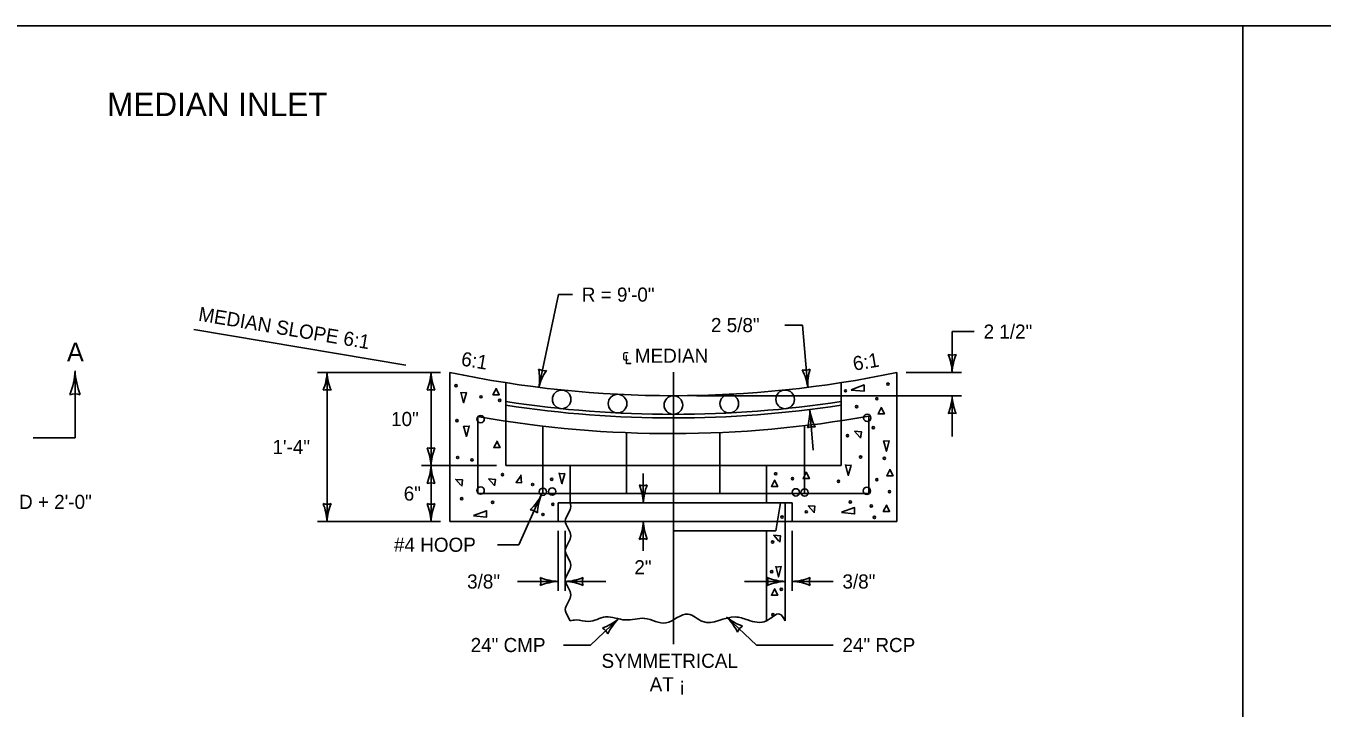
# Model space of a CAD drawing. Extents: x 49991.4 to 50021, y 49987.6 to 50011.4.
# Drawn here: x 50002.9 to 50008.4, y 49996.1 to 49999 of the extents above; entities that cross this region are included whole.
import ezdxf

# ---------------------------------------------------------------- set-up
doc = ezdxf.new("R2010")
doc.units = 0
for name, color, linetype in [('Level 1', 7, 'Continuous'), ('Level 2', 7, 'Continuous'), ('Level 3', 7, 'Continuous'), ('Level 4', 7, 'Continuous'), ('Level 5', 7, 'Continuous'), ('Level 6', 7, 'Continuous')]:
    doc.layers.add(name, color=color, linetype=linetype)

msp = doc.modelspace()

# ---------------------------------------------------------------- linework, layer by layer
at = {"layer": 'Level 1'}
for p, q in [((50008.0668, 49998.9992), (50008.0668, 49987.7988)), ((50004.6973, 49996.894), (50004.6973, 49997.5274)), ((50006.5972, 49996.894), (50006.5972, 49997.5274)), ((50004.9348, 49997.1316), (50004.9348, 49997.4839)), ((50006.3597, 49997.1316), (50006.3597, 49997.4839)), ((50004.816, 49997.0127), (50004.816, 49997.3383)), ((50005.9886, 49997.3617), (50005.9886, 49997.3617)), ((50006.4785, 49997.0127), (50006.4785, 49997.3419)), ((50005.0926, 49997.0127), (50005.0926, 49997.299)), ((50006.2049, 49997.0127), (50006.2049, 49997.3012)), ((50005.4475, 49997.0126), (50005.4475, 49997.271)), ((50005.8451, 49997.0127), (50005.8451, 49997.272)), ((50004.9348, 49997.1316), (50006.3597, 49997.1316)), ((50005.2078, 49996.9732), (50005.2078, 49997.1316)), ((50006.0431, 49996.9732), (50006.0431, 49997.1316)), ((50004.816, 49997.0127), (50006.4785, 49997.0127)), ((50005.1573, 49996.9732), (50005.1573, 49996.894)), ((50005.1573, 49996.9732), (50005.2079, 49996.9732)), ((50005.2079, 49996.9732), (50006.1222, 49996.9732)), ((50006.0826, 49996.8544), (50006.1025, 49996.9732)), ((50006.1222, 49996.9732), (50006.1222, 49996.4721)), ((50006.1222, 49996.9732), (50006.1523, 49996.9732)), ((50006.1523, 49996.9732), (50006.1523, 49996.894)), ((50005.1912, 49996.9107), (50005.2078, 49996.9441)), ((50004.6973, 49996.894), (50005.1573, 49996.894)), ((50005.2078, 49996.848), (50005.1912, 49996.8813)), ((50006.0431, 49996.8544), (50005.6472, 49996.8544)), ((50006.0431, 49996.8544), (50006.0431, 49996.4721)), ((50006.0431, 49996.8544), (50006.0826, 49996.8544)), ((50006.1523, 49996.894), (50006.5972, 49996.894)), ((50005.1912, 49996.7853), (50005.2078, 49996.8187)), ((50005.2078, 49996.7227), (50005.1912, 49996.756)), ((50005.1912, 49996.66), (50005.2078, 49996.6934)), ((50005.2078, 49996.5974), (50005.1912, 49996.6307)), ((50005.1912, 49996.5347), (50005.2078, 49996.5681)), ((50005.2078, 49996.4721), (50005.1912, 49996.5054))]:
    msp.add_line(p, q, dxfattribs=at)
msp.add_lwpolyline([(49999.3835, 49998.9992), (50016.7501, 49998.9992), (50016.7501, 49987.7988), (49999.3835, 49987.7988)], close=True, dxfattribs=at)
for points in [[(50004.8956, 49997.4608), (50004.8803, 49997.4322), (50004.9073, 49997.4322), (50004.8939, 49997.4592)], [(50006.4023, 49997.4541), (50006.4579, 49997.4744), (50006.4579, 49997.4474), (50006.4023, 49997.4525)], [(50004.7439, 49997.4407), (50004.7675, 49997.4424), (50004.7557, 49997.3986), (50004.7439, 49997.4441)], [(50004.8156, 49997.3385), (50004.8184, 49997.3413), (50004.8186, 49997.3415)], [(50006.532, 49997.38), (50006.5169, 49997.3513), (50006.5439, 49997.3513), (50006.5304, 49997.3783)], [(50004.7557, 49997.2974), (50004.7793, 49997.2991), (50004.7675, 49997.2553), (50004.7557, 49997.3007)], [(50004.8989, 49997.2367), (50004.8838, 49997.2081), (50004.9107, 49997.2081), (50004.8973, 49997.2351)], [(50006.4428, 49997.2485), (50006.4461, 49997.2755), (50006.4175, 49997.2772), (50006.4394, 49997.2519)], [(50006.5404, 49997.2351), (50006.564, 49997.2368), (50006.5523, 49997.1929), (50006.5404, 49997.2385)], [(50006.3786, 49997.1322), (50006.4022, 49997.134), (50006.3905, 49997.0901), (50006.3786, 49997.1357)], [(50006.5691, 49997.117), (50006.5539, 49997.0884), (50006.5809, 49997.0884), (50006.5674, 49997.1153)], [(50004.7473, 49997.0446), (50004.7506, 49997.0716), (50004.722, 49997.0732), (50004.7439, 49997.048)], [(50004.8871, 49997.0462), (50004.8905, 49997.0732), (50004.8618, 49997.0749), (50004.8838, 49997.0497)], [(50005.0003, 49997.0891), (50004.9783, 49997.0604), (50005.0019, 49997.0587), (50004.9986, 49997.0924)], [(50005.1619, 49997.0968), (50005.1855, 49997.0986), (50005.1737, 49997.0547), (50005.1619, 49997.1002)], [(50006.0787, 49997.0715), (50006.0636, 49997.0429), (50006.0905, 49997.0429), (50006.0771, 49997.0698)], [(50006.2135, 49997.1052), (50006.1984, 49997.0767), (50006.2253, 49997.0767), (50006.2118, 49997.1036)], [(50006.2455, 49996.9316), (50006.2489, 49996.9586), (50006.2202, 49996.9602), (50006.2421, 49996.935)], [(50006.3619, 49996.9333), (50006.4175, 49996.9536), (50006.4175, 49996.9267), (50006.3619, 49996.9317)], [(50006.5539, 49996.9653), (50006.5388, 49996.9367), (50006.5658, 49996.9367), (50006.5523, 49996.9637)], [(50004.7979, 49996.9198), (50004.8534, 49996.9401), (50004.8534, 49996.9131), (50004.7979, 49996.9182)], [(50006.0989, 49996.8069), (50006.1023, 49996.8339), (50006.0736, 49996.8356), (50006.0955, 49996.8103)], [(50006.0821, 49996.7007), (50006.1057, 49996.7024), (50006.0939, 49996.6587), (50006.0821, 49996.7041)], [(50006.0787, 49996.6097), (50006.0636, 49996.5811), (50006.0905, 49996.5811), (50006.0771, 49996.6081)]]:
    msp.add_lwpolyline(points, dxfattribs=at)
for centre in [(50004.7237, 49997.471), (50006.3787, 49997.4491), (50006.559, 49997.4777), (50004.8299, 49997.4238), (50004.9091, 49997.4086), (50006.5118, 49997.4154), (50006.4259, 49997.3817), (50004.727, 49997.3227), (50006.4966, 49997.2924), (50006.3871, 49997.2587), (50004.7304, 49997.1659), (50006.4427, 49997.1677), (50004.7911, 49997.1559), (50006.5438, 49997.1626), (50004.9209, 49997.0935), (50005.1299, 49997.0732), (50006.082, 49997.0968), (50006.1533, 49997.076), (50006.349, 49997.0648), (50006.5118, 49997.0716), (50005.049, 49997.0514), (50006.5657, 49997.021), (50004.7473, 49996.9907), (50004.8787, 49996.9755), (50005.1349, 49996.9671), (50006.3989, 49996.9772), (50006.4882, 49996.9604), (50005.0925, 49996.924), (50006.109, 49996.9131), (50006.2118, 49996.9351), (50006.5017, 49996.9115), (50006.0686, 49996.807), (50006.0652, 49996.6806), (50006.1056, 49996.6064), (50006.0703, 49996.4985)]:
    msp.add_circle(centre, 0.00476, dxfattribs=at)
for centre, major_axis, start_param, end_param in [((50005.6472, 50002.0379), (0, -4.6095), 6.075601, 6.49077), ((50005.6472, 50002.0379), (0, -4.6886), 6.130631, 6.435739), ((50005.6396, 50002.0353), (0, -4.7678), 6.110622, 6.460063), ((50005.6472, 50002.0323), (0, -4.6985), 6.130999, 6.435415), ((50005.1785, 49996.9587), (0, -0.0328), 1.107175, 2.034314), ((50005.2205, 49996.896), (0, 0.0328), 1.107223, 2.034348), ((50005.1785, 49996.8334), (0, -0.0328), 1.107175, 2.034314), ((50005.2205, 49996.7707), (0, 0.0328), 1.107223, 2.034348), ((50005.1785, 49996.708), (0, -0.0328), 1.107175, 2.034314), ((50005.2205, 49996.6454), (0, 0.0328), 1.107223, 2.034348), ((50005.1785, 49996.5827), (0, -0.0328), 1.107175, 2.034314), ((50005.2205, 49996.5201), (0, 0.0328), 1.107223, 2.034348)]:
    msp.add_ellipse(centre, major_axis=major_axis, ratio=0.99996, start_param=start_param, end_param=end_param, dxfattribs=at)
for centre, major_axis in [((50005.1723, 49997.4129), (0, 0.0396)), ((50006.1222, 49997.4129), (0, 0.0396)), ((50005.4098, 49997.3949), (0, 0.0396)), ((50005.6472, 49997.3888), (0, 0.0396)), ((50005.8847, 49997.3949), (0, 0.0396)), ((50004.828, 49997.329), (0, 0.0156)), ((50006.4712, 49997.3341), (0, 0.0156)), ((50004.828, 49997.0256), (0, 0.0156)), ((50005.0926, 49997.0206), (0, 0.0156)), ((50005.1322, 49997.0214), (0, 0.0156)), ((50006.1674, 49997.018), (0, 0.0156)), ((50006.2049, 49997.0172), (0, 0.0156)), ((50006.4695, 49997.024), (0, 0.0156))]:
    msp.add_ellipse(centre, major_axis=major_axis, ratio=0.99996, dxfattribs=at)
msp.add_spline([(50005.2078, 49996.4721), (50005.2335, 49996.4761), (50005.2868, 49996.4698), (50005.3588, 49996.4886), (50005.4435, 49996.4761), (50005.5248, 49996.4823), (50005.6157, 49996.4636), (50005.7097, 49996.5011), (50005.7716, 49996.4693), (50005.9102, 49996.4886), (50005.9634, 49996.4761), (50006.0431, 49996.4721), (50006.0981, 49996.5011), (50006.1222, 49996.4721)], degree=3, dxfattribs=at)
at = {"layer": 'Level 2'}
msp.add_line((50004.5104, 49997.5587), (50003.6091, 49997.7095), dxfattribs=at)
at = {"layer": 'Level 3'}
for p, q in [((50005.1582, 49997.858), (50005.0753, 49997.4641)), ((50005.2179, 49997.858), (50005.1582, 49997.858)), ((50006.1209, 49997.7285), (50006.1959, 49997.7285)), ((50006.1959, 49997.7285), (50006.2181, 49997.4639)), ((50006.832, 49997.7008), (50006.832, 49997.5274)), ((50006.832, 49997.7008), (50006.9256, 49997.7008)), ((50004.6573, 49997.5274), (50004.1352, 49997.5274)), ((50004.1752, 49996.894), (50004.1752, 49997.5274)), ((50004.617, 49997.5274), (50004.617, 49997.1318)), ((50006.6372, 49997.5274), (50006.872, 49997.5274)), ((50005.7472, 49997.4284), (50006.872, 49997.4284)), ((50006.832, 49997.4284), (50006.832, 49997.255)), ((50006.2264, 49997.3689), (50006.2414, 49997.1968)), ((50004.8948, 49997.1316), (50004.577, 49997.1316)), ((50004.617, 49997.1318), (50004.617, 49996.894)), ((50005.5192, 49996.9732), (50005.5192, 49997.0975)), ((50005.0855, 49997.0068), (50004.9905, 49996.7954)), ((50004.6573, 49996.894), (50004.1352, 49996.894)), ((50005.1573, 49996.854), (50005.1573, 49996.5994)), ((50005.1871, 49996.854), (50005.1871, 49996.5994)), ((50005.5192, 49996.894), (50005.5192, 49996.7697)), ((50006.1523, 49996.854), (50006.1523, 49996.5994)), ((50004.9905, 49996.7954), (50004.9001, 49996.7954)), ((50005.1573, 49996.6394), (50004.9839, 49996.6394)), ((50005.1871, 49996.6394), (50005.3605, 49996.6394)), ((50006.1222, 49996.6394), (50005.9488, 49996.6394)), ((50006.1523, 49996.6394), (50006.3257, 49996.6394)), ((50005.4129, 49996.48), (50005.295, 49996.3694)), ((50005.8736, 49996.4878), (50005.9997, 49996.3694)), ((50005.1799, 49996.3694), (50005.295, 49996.3694)), ((50005.9997, 49996.3694), (50006.3257, 49996.3694))]:
    msp.add_line(p, q, dxfattribs=at)
for centre, radius, start, end in [((50004.3949, 49997.5366), 0.2223, 337.456, 357.6395), ((50004.8497, 49997.5389), 0.233, 182.8273, 202.0772), ((50005.1017, 49997.5895), 0.0548, 240.2517, 275.974), ((50004.8452, 49997.5007), 0.233, 350.9402, 10.19), ((50005.2908, 49997.4093), 0.2223, 145.5689, 165.7524), ((50006.2074, 49997.5917), 0.0548, 256.9218, 292.6442), ((50005.9871, 49997.4331), 0.233, 7.6103, 26.8602), ((50006.4402, 49997.4733), 0.2223, 162.239, 182.4225), ((50004.617, 49997.3992), 0.0548, 72.1388, 107.8612), ((50004.617, 49997.2598), 0.0548, 252.1388, 287.8612), ((50004.3843, 49997.1201), 0.233, 2.8273, 22.0772), ((50004.8391, 49997.1224), 0.2223, 157.456, 177.6395), ((50004.3949, 49997.1408), 0.2223, 337.456, 357.6395), ((50004.8497, 49997.1431), 0.233, 182.8273, 202.0772), ((50004.617, 49997.0034), 0.0548, 72.1388, 107.8612), ((50004.8867, 49997.1062), 0.2223, 313.2474, 333.4309), ((50005.3025, 49996.9218), 0.233, 158.6187, 177.8686), ((50004.617, 49997.0222), 0.0548, 252.1388, 287.8612), ((50004.3843, 49996.8825), 0.233, 2.8273, 22.0772), ((50004.8391, 49996.8848), 0.2223, 157.456, 177.6395), ((50005.0329, 49996.8898), 0.0548, 47.9302, 83.6526), ((50005.1665, 49996.8615), 0.2223, 247.456, 267.6395), ((50005.0291, 49996.6394), 0.0548, 342.1388, 17.8612), ((50005.1688, 49996.4067), 0.233, 92.8273, 112.0772), ((50005.1756, 49996.8721), 0.233, 272.8273, 292.0772), ((50005.1779, 49996.4173), 0.2223, 67.456, 87.6395), ((50005.3153, 49996.6394), 0.0548, 162.1388, 197.8612), ((50006.1314, 49996.8615), 0.2223, 247.456, 267.6395), ((50005.994, 49996.6394), 0.0548, 342.1388, 17.8612), ((50006.1337, 49996.4067), 0.233, 92.8273, 112.0772), ((50006.1408, 49996.8721), 0.233, 272.8273, 292.0772), ((50006.1431, 49996.4173), 0.2223, 67.456, 87.6395), ((50006.2805, 49996.6394), 0.0548, 162.1388, 197.8612)]:
    msp.add_arc(centre, radius, start, end, dxfattribs=at)
for centre, major_axis, start_param, end_param in [((50006.832, 49997.6556), (0, -0.0548), 5.971449, 6.594922), ((50006.5993, 49997.5159), (0, 0.233), 4.761735, 5.097708), ((50007.0541, 49997.5182), (0, 0.2223), 1.177329, 1.529598), ((50002.8079, 49997.5466), (0, -0.2964), 1.177329, 1.529598), ((50003.4144, 49997.5497), (0, -0.3107), 4.761735, 5.097708), ((50003.9531, 49997.5366), (0, -0.2223), 1.177329, 1.529598), ((50004.4079, 49997.5389), (0, -0.233), 4.761735, 5.097708), ((50004.1752, 49997.3992), (0, 0.0548), 5.971449, 6.594922), ((50003.1041, 49997.3634), (0, 0.073), 5.971449, 6.594922), ((50006.6099, 49997.4376), (0, -0.2223), 1.177329, 1.529598), ((50007.0647, 49997.4399), (0, -0.233), 4.761735, 5.097708), ((50006.0043, 49997.3579), (0, -0.2223), 1.271255, 1.623523), ((50006.4569, 49997.4029), (0, -0.233), 4.85566, 5.191633), ((50006.832, 49997.3002), (0, 0.0548), 5.971449, 6.594922), ((50006.2383, 49997.242), (0, 0.0548), 6.065374, 6.688847), ((50005.5192, 49997.1014), (0, -0.0548), 5.971449, 6.594922), ((50005.2865, 49996.9617), (0, 0.233), 4.761735, 5.097708), ((50005.7413, 49996.964), (0, 0.2223), 1.177329, 1.529598), ((50004.1752, 49997.0222), (0, -0.0548), 5.971449, 6.594922), ((50003.9425, 49996.8825), (0, 0.233), 4.761735, 5.097708), ((50004.3973, 49996.8848), (0, 0.2223), 1.177329, 1.529598), ((50005.2971, 49996.9032), (0, -0.2223), 1.177329, 1.529598), ((50005.7519, 49996.9055), (0, -0.233), 4.761735, 5.097708), ((50005.5192, 49996.7658), (0, 0.0548), 5.971449, 6.594922), ((50005.2703, 49996.6507), (0, -0.2223), 0.343529, 0.695798), ((50005.5778, 49996.3154), (0, 0.233), 0.786342, 1.122315), ((50005.7191, 49996.3279), (0, 0.2223), 5.162843, 5.515112), ((50006.0196, 49996.6694), (0, -0.233), 5.605656, 5.941629), ((50005.3179, 49996.3939), (0, 0.0548), 5.137648, 5.761121), ((50005.9694, 49996.4026), (0, 0.0548), 0.532185, 1.155658)]:
    msp.add_ellipse(centre, major_axis=major_axis, ratio=0.99996, start_param=start_param, end_param=end_param, dxfattribs=at)
at = {"layer": 'Level 4'}
msp.add_line((50005.1573, 49996.894), (50006.1523, 49996.894), dxfattribs=at)
at = {"layer": 'Level 5'}
msp.add_line((50005.6472, 49996.3725), (50005.6472, 49997.5284), dxfattribs=at)
at = {"layer": 'Level 6'}
for q in [(50003.1041, 49997.5344), (50002.926, 49997.2494)]:
    msp.add_line((50003.1041, 49997.2494), q, dxfattribs=at)

# ---------------------------------------------------------------- texts
at = {"layer": 'Level 2'}
for s, height, p in [('MEDIAN INLET', 0.1, (50003.2405, 49998.6161)), ('R = 9\'-0"', 0.06, (50005.2579, 49997.828)), ('2 5/8"', 0.06, (50005.8067, 49997.6985)), ('2 1/2"', 0.06, (50006.9656, 49997.6708)), ('A', 0.08, (50003.0698, 49997.5744)), ('℄ MEDIAN', 0.06, (50005.4285, 49997.5684)), ('10"', 0.06, (50004.4472, 49997.2996)), ('1\'-4"', 0.06, (50003.943, 49997.1807)), ('D + 2\'-0"', 0.06, (50002.866, 49996.9475)), ('6"', 0.06, (50004.501, 49996.9829)), ('#4 HOOP', 0.06, (50004.4596, 49996.7654)), ('2"', 0.06, (50005.4812, 49996.6697)), ('3/8"', 0.06, (50004.7704, 49996.6094)), ('3/8"', 0.06, (50006.3657, 49996.6094)), ('24" CMP', 0.06, (50004.7854, 49996.3394)), ('24" RCP', 0.06, (50006.3657, 49996.3394)), ('SYMMETRICAL', 0.06, (50005.3417, 49996.2725)), ('AT ¡', 0.06, (50005.5464, 49996.1725))]:
    msp.add_text(s, height=height, dxfattribs=at).set_placement(p)
for s, height, rotation, p in [('MEDIAN SLOPE 6:1', 0.059999, 350.5028, (50003.6254, 49997.7473)), ('6:1', 0.06, 350.5028, (50004.742, 49997.5571)), ('6:1', 0.06, 9.4972, (50006.4153, 49997.5342))]:
    msp.add_text(s, height=height, rotation=rotation, dxfattribs=at).set_placement(p)

doc.saveas('drawing.dxf')
